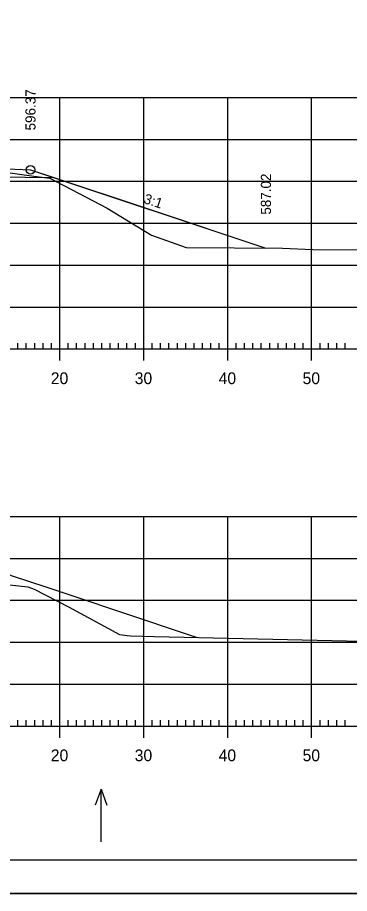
# Model space of a CAD drawing. Extents: x 961436 to 1372525, y 380079 to 2027791.
# Drawn here: x 1370205.5 to 1370245, y 380109.1 to 380213.6 of the extents above; entities that cross this region are included whole.
import ezdxf

# ---------------------------------------------------------------- set-up
doc = ezdxf.new("R2010")
doc.units = 0
for name, color, linetype in [('R_Alt Surface', 7, 'Continuous'), ('R_Axis', 7, 'Continuous'), ('R_Axis Annot', 7, 'Continuous'), ('R_Exist Surface', 7, 'Continuous'), ('R_Fin Surface', 7, 'Continuous'), ('R_Fin Surface Annot', 7, 'Continuous'), ('R_Grid', 7, 'Continuous'), ('R_No Plot', 7, 'Continuous'), ('R_Water Annot', 7, 'Continuous')]:
    doc.layers.add(name, color=color, linetype=linetype)

msp = doc.modelspace()

# ---------------------------------------------------------------- linework, layer by layer
at = {"layer": 'R_Alt Surface'}
msp.add_lwpolyline([(1370171.03, 380194.44), (1370181.49, 380194.65), (1370181.5, 380195.56), (1370190.5, 380195.74), (1370199.5, 380195.56), (1370199.51, 380194.65), (1370209.77, 380194.51)], dxfattribs=at)
at = {"layer": 'R_Axis'}
for p, q in [((1370205.5, 380174.06), (1370205.5, 380174.76)), ((1370206.5, 380174.06), (1370206.5, 380174.76)), ((1370207.5, 380174.06), (1370207.5, 380174.76)), ((1370208.5, 380174.06), (1370208.5, 380174.76)), ((1370209.5, 380174.06), (1370209.5, 380174.76)), ((1370210.5, 380172.66), (1370210.5, 380175.46)), ((1370211.5, 380174.06), (1370211.5, 380174.76)), ((1370212.5, 380174.06), (1370212.5, 380174.76)), ((1370213.5, 380174.06), (1370213.5, 380174.76)), ((1370214.5, 380174.06), (1370214.5, 380174.76)), ((1370215.5, 380174.06), (1370215.5, 380174.76)), ((1370216.5, 380174.06), (1370216.5, 380174.76)), ((1370217.5, 380174.06), (1370217.5, 380174.76)), ((1370218.5, 380174.06), (1370218.5, 380174.76)), ((1370219.5, 380174.06), (1370219.5, 380174.76)), ((1370220.5, 380172.66), (1370220.5, 380175.46)), ((1370221.5, 380174.06), (1370221.5, 380174.76)), ((1370222.5, 380174.06), (1370222.5, 380174.76)), ((1370223.5, 380174.06), (1370223.5, 380174.76)), ((1370224.5, 380174.06), (1370224.5, 380174.76)), ((1370225.5, 380174.06), (1370225.5, 380174.76)), ((1370226.5, 380174.06), (1370226.5, 380174.76)), ((1370227.5, 380174.06), (1370227.5, 380174.76)), ((1370228.5, 380174.06), (1370228.5, 380174.76)), ((1370229.5, 380174.06), (1370229.5, 380174.76)), ((1370230.5, 380172.66), (1370230.5, 380175.46)), ((1370231.5, 380174.06), (1370231.5, 380174.76)), ((1370232.5, 380174.06), (1370232.5, 380174.76)), ((1370233.5, 380174.06), (1370233.5, 380174.76)), ((1370234.5, 380174.06), (1370234.5, 380174.76)), ((1370235.5, 380174.06), (1370235.5, 380174.76)), ((1370236.5, 380174.06), (1370236.5, 380174.76)), ((1370237.5, 380174.06), (1370237.5, 380174.76)), ((1370238.5, 380174.06), (1370238.5, 380174.76)), ((1370239.5, 380174.06), (1370239.5, 380174.76)), ((1370240.5, 380172.66), (1370240.5, 380175.46)), ((1370241.5, 380174.06), (1370241.5, 380174.76)), ((1370242.5, 380174.06), (1370242.5, 380174.76)), ((1370243.5, 380174.06), (1370243.5, 380174.76)), ((1370244.5, 380174.06), (1370244.5, 380174.76)), ((1370050.5, 380174.06), (1370330.5, 380174.06)), ((1370205.5, 380129.06), (1370205.5, 380129.76)), ((1370206.5, 380129.06), (1370206.5, 380129.76)), ((1370207.5, 380129.06), (1370207.5, 380129.76)), ((1370208.5, 380129.06), (1370208.5, 380129.76)), ((1370209.5, 380129.06), (1370209.5, 380129.76)), ((1370210.5, 380127.66), (1370210.5, 380130.46)), ((1370211.5, 380129.06), (1370211.5, 380129.76)), ((1370212.5, 380129.06), (1370212.5, 380129.76)), ((1370213.5, 380129.06), (1370213.5, 380129.76)), ((1370214.5, 380129.06), (1370214.5, 380129.76)), ((1370215.5, 380129.06), (1370215.5, 380129.76)), ((1370216.5, 380129.06), (1370216.5, 380129.76)), ((1370217.5, 380129.06), (1370217.5, 380129.76)), ((1370218.5, 380129.06), (1370218.5, 380129.76)), ((1370219.5, 380129.06), (1370219.5, 380129.76)), ((1370220.5, 380127.66), (1370220.5, 380130.46)), ((1370221.5, 380129.06), (1370221.5, 380129.76)), ((1370222.5, 380129.06), (1370222.5, 380129.76)), ((1370223.5, 380129.06), (1370223.5, 380129.76)), ((1370224.5, 380129.06), (1370224.5, 380129.76)), ((1370225.5, 380129.06), (1370225.5, 380129.76)), ((1370226.5, 380129.06), (1370226.5, 380129.76)), ((1370227.5, 380129.06), (1370227.5, 380129.76)), ((1370228.5, 380129.06), (1370228.5, 380129.76)), ((1370229.5, 380129.06), (1370229.5, 380129.76)), ((1370230.5, 380127.66), (1370230.5, 380130.46)), ((1370231.5, 380129.06), (1370231.5, 380129.76)), ((1370232.5, 380129.06), (1370232.5, 380129.76)), ((1370233.5, 380129.06), (1370233.5, 380129.76)), ((1370234.5, 380129.06), (1370234.5, 380129.76)), ((1370235.5, 380129.06), (1370235.5, 380129.76)), ((1370236.5, 380129.06), (1370236.5, 380129.76)), ((1370237.5, 380129.06), (1370237.5, 380129.76)), ((1370238.5, 380129.06), (1370238.5, 380129.76)), ((1370239.5, 380129.06), (1370239.5, 380129.76)), ((1370240.5, 380127.66), (1370240.5, 380130.46)), ((1370241.5, 380129.06), (1370241.5, 380129.76)), ((1370242.5, 380129.06), (1370242.5, 380129.76)), ((1370243.5, 380129.06), (1370243.5, 380129.76)), ((1370244.5, 380129.06), (1370244.5, 380129.76)), ((1370050.5, 380129.06), (1370330.5, 380129.06))]:
    msp.add_line(p, q, dxfattribs=at)
at = {"layer": 'R_Exist Surface'}
for points in [[(1370199.96, 380195.71), (1370207.39, 380194.68), (1370209.29, 380194.42), (1370216.12, 380190.87), (1370221.43, 380187.63), (1370225.56, 380186.15), (1370237.03, 380186.07), (1370240.63, 380185.93), (1370253.76, 380185.88)], [(1370129.95, 380141.09), (1370137.23, 380141.23), (1370154.6, 380141.59), (1370161.26, 380141.72), (1370167.44, 380142.01), (1370169.57, 380143.3), (1370172.15, 380145.01), (1370178.27, 380145.76), (1370178.48, 380145.79), (1370178.67, 380145.8), (1370185.4, 380146.16), (1370189.92, 380146.4), (1370190.32, 380146.41), (1370198.51, 380146.62), (1370201.9, 380146.2), (1370206.68, 380145.66), (1370207.43, 380145.38), (1370211.52, 380143.3), (1370217.62, 380140), (1370218.51, 380139.85), (1370218.93, 380139.84), (1370221.76, 380139.76), (1370248.2, 380139.15)]]:
    msp.add_lwpolyline(points, dxfattribs=at)
at = {"layer": 'R_Fin Surface'}
for points in [[(1370147.28, 380186.52), (1370171.03, 380194.44), (1370174, 380195.43), (1370181.5, 380195.73), (1370190.5, 380195.91), (1370199.5, 380195.73), (1370207, 380195.43), (1370209.77, 380194.51), (1370220.89, 380190.81), (1370235.05, 380186.08)], [(1370147.28, 380186.52), (1370171.03, 380194.44), (1370171.5, 380194.6), (1370174, 380195.43), (1370181.5, 380195.73), (1370190.5, 380195.91), (1370199.5, 380195.73), (1370207, 380195.43), (1370209.5, 380194.6), (1370209.98, 380194.44), (1370232.55, 380186.91), (1370235.05, 380186.08)], [(1370172.66, 380144.93), (1370173.32, 380145.15), (1370175.5, 380145.88), (1370176.21, 380146.12), (1370181.5, 380146.33), (1370190.5, 380146.65), (1370199.5, 380146.88), (1370204.5, 380147.09), (1370204.8, 380147), (1370208.95, 380145.61), (1370208.96, 380145.61), (1370213, 380144.27), (1370217.25, 380142.85), (1370226.86, 380139.64)]]:
    msp.add_lwpolyline(points, dxfattribs=at)
at = {"layer": 'R_Grid'}
for p, q in [((1370050.5, 380204.06), (1370330.5, 380204.06)), ((1370210.5, 380174.06), (1370210.5, 380204.06)), ((1370220.5, 380174.06), (1370220.5, 380204.06)), ((1370230.5, 380174.06), (1370230.5, 380204.06)), ((1370240.5, 380174.06), (1370240.5, 380204.06)), ((1370050.5, 380199.06), (1370330.5, 380199.06)), ((1370050.5, 380194.06), (1370330.5, 380194.06)), ((1370050.5, 380189.06), (1370330.5, 380189.06)), ((1370050.5, 380184.06), (1370330.5, 380184.06)), ((1370050.5, 380179.06), (1370330.5, 380179.06)), ((1370050.5, 380174.06), (1370330.5, 380174.06)), ((1370050.5, 380154.06), (1370330.5, 380154.06)), ((1370210.5, 380129.06), (1370210.5, 380154.06)), ((1370220.5, 380129.06), (1370220.5, 380154.06)), ((1370230.5, 380129.06), (1370230.5, 380154.06)), ((1370240.5, 380129.06), (1370240.5, 380154.06)), ((1370050.5, 380149.06), (1370330.5, 380149.06)), ((1370050.5, 380144.06), (1370330.5, 380144.06)), ((1370050.5, 380139.06), (1370330.5, 380139.06)), ((1370050.5, 380134.06), (1370330.5, 380134.06)), ((1370050.5, 380129.06), (1370330.5, 380129.06))]:
    msp.add_line(p, q, dxfattribs=at)
at = {"layer": 'R_No Plot'}
for p, q in [((1370348.68, 380113.06), (1370032.5, 380113.06)), ((1370020.1, 380109.08), (1370353.44, 380109.08))]:
    msp.add_line(p, q, dxfattribs=at)
for points in [[(1370020.1, 380322.41), (1370353.44, 380322.41), (1370353.44, 380109.08), (1370020.1, 380109.08)], [(1370266.42, 380318.52), (1370286.04, 380318.52), (1370286.04, 380308.64), (1370302.16, 380308.64), (1370325.36, 380308.64), (1370325.48, 380280.48), (1370348.68, 380280.48), (1370348.68, 380113.06), (1370032.5, 380113.06), (1370032.5, 380318.52)]]:
    msp.add_lwpolyline(points, close=True, dxfattribs=at)
msp.add_circle((1370207, 380195.43), 0.5, dxfattribs=at)
at = {"layer": 'R_Water Annot'}
for p, q in [((1370215.41, 380121.52), (1370214.71, 380119.6)), ((1370215.41, 380115.24), (1370215.41, 380121.52)), ((1370215.41, 380121.52), (1370216.11, 380119.6))]:
    msp.add_line(p, q, dxfattribs=at)

# ---------------------------------------------------------------- texts
at = {"layer": 'R_Axis Annot'}
for s, p in [('20', (1370209.42, 380169.86)), ('30', (1370219.42, 380169.86)), ('40', (1370229.42, 380169.86)), ('50', (1370239.42, 380169.86)), ('20', (1370209.42, 380124.86)), ('30', (1370219.42, 380124.86)), ('40', (1370229.42, 380124.86)), ('50', (1370239.42, 380124.86))]:
    msp.add_text(s, height=1.4, dxfattribs=at).set_placement(p)
at = {"layer": 'R_Fin Surface Annot'}
for s, rotation, p in [('596.37', 90, (1370207.6, 380200.13)), ('587.02', 90, (1370235.65, 380190.08)), ('3:1', 341.5651, (1370220.4, 380191.49))]:
    msp.add_text(s, height=1.2, rotation=rotation, dxfattribs=at).set_placement(p)

doc.saveas('drawing.dxf')
